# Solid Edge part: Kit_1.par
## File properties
Author: bmolnar
Last saved by: bmolnar
Revision: 78
Sűrűség: 0,000 kg/m^3
Pontosság: 0,990
Username: bmolnar
Dokumentum tartalom típus: 0
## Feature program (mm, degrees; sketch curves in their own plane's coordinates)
base feature "unnamed BaseFeature 1"
thread "unnamed Thread 1"
thread "unnamed Thread 2"
thread "unnamed Thread 3"
thread "unnamed Thread 4"
sketch for "Furat_1" plane through (56.65, 0, -134.65) normal (-1, 0, 0) x-axis (0, -1, 0)
  hole centre (0, 47.65) bore radius 4.283
hole "Furat_1" nominal diameter 9.728 finite  ThreadDepth = 12 mm
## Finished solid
Body 1: solid body, 320 faces, 792 edges, 492 vertices.
  Faces by surface: plane 145, cylinder 82, swept 56, cone 25, torus 11, spline 1
  Edges by curve: line 446, circle 180, spline 136, ellipse 28, curve on surface 2
Bounding box of the edges (mm; curved faces can reach further): 113.300 x 113.300 x 19.500, from (-56.65, -56.65, -97.5) to (56.65, 56.65, -78).
Cylindrical faces by radius (mm): R0.2 x48, R0.2006 x2, R0.2007 x2, R4.188 x4, R4.283 x1, R6.35 x4, R6.55 x4, R6.75 x4, R12.8 x1, R13.45 x1, R14 x1, R14.9 x1, R15 x1, R51.85 x8
Conical faces (half-angle, radius in mm at the cone's reference point): 0.5 deg R12.25 x4, 0.5 deg R35 x2, 3 deg R14.95 x1, 7 deg R14.2695 x1, 14 deg R12.65 x1, 14 deg R13.057 x1, 17 deg R12.65 x1, 23 deg R13.4211 x1, 42.5 deg R12.637 x1, 45 deg R4.588 x8, 45 deg R13.6 x1, 84 deg R13.012 x1, 85 deg R14.6625 x1, 87 deg R12.7157 x1
Toroidal faces (ring radius, tube radius in mm): R6.05 r0.3 x2, R6.15 r0.2 x6, R13.4008 r0.225 x1, R13.8914 r0.325 x1, R14.7 r0.2 x1
Planar faces by outward normal: +x 17, +y 14, +z 2, -x 14, -y 16, -z 19, oblique 63
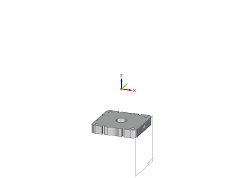
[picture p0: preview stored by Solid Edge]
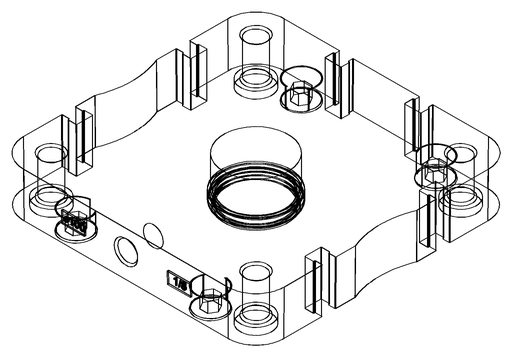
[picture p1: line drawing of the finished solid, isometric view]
